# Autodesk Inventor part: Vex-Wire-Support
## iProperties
Created: 2007-08
Part Number: Vex-Wire-Support
Document SubType Name: Modeling
Density: 1 g/cm^3
Mass: 0.120142 g
Surface Area: 2.78928 cm^2
Volume: 0.120142 cm^3
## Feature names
1. Base1
